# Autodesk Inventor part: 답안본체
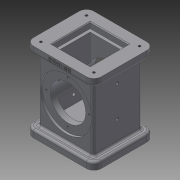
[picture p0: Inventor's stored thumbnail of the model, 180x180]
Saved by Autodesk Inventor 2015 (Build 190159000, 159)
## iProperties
Created: 2017-08
Part Number: 답안본체
Material: 일반
Document SubType Name: Modeling
Designer: Administrator
Density: 1 g/cm^3
Appearance: 기본값
Author: Administrator
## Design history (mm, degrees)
sketch "스케치1"
  geometry: L1 (-46, 41)-(46, 41); L2 (46, 41)-(46, -41); L3 (46, -41)-(-46, -41); L4 (-46, -41)-(-46, 41); L5 (-46, 41)-(46, -41); 2 further points
  constraints: 10 end point, 2 parallel, 1 coincident, 1 horizontal, 1 midpoint, 1 perpendicular
  dimensions: "d0" = 92 distance of L1.start L1.end; "d1" = 82 distance of L3.end L1.start
extrude "돌출1" new body sketch "스케치1" distance "d2" = 10; taper "d3" = 0 deg
sketch "스케치2"
  geometry: L1 (-37, 33)-(37, 33); L2 (37, 33)-(37, -33); L3 (37, -33)-(-37, -33); L4 (-37, -33)-(-37, 33); L5 (-37, 33)-(37, -33); 2 further points
  constraints: 10 end point, 2 parallel, 1 coincident, 1 horizontal, 1 midpoint, 1 perpendicular
  dimensions: "d4" = 74 distance of L1.start L1.end; "d5" = 66 distance of L3.end L1.start
extrude "돌출2" join sketch "스케치2" distance "d6" = 88; taper "d7" = 0 deg
sketch "스케치3"
  geometry: L1 (37, 33)-(37, -33) reference; L2 (37, -33)-(-37, -33) reference; L3 (-37, -33)-(-37, 33) reference; L4 (-37, 33)-(37, 33) reference; L5 (46, 41)-(-46, 41) reference; L6 (-46, 41)-(-46, -41) reference; L7 (-46, -41)-(46, -41) reference; L8 (46, -41)-(46, 41) reference; L9 (-46, 41)-(46, 41); L10 (46, 41)-(46, -41); L11 (46, -41)-(-46, -41); L12 (-46, -41)-(-46, 41); 1 further point
  constraints: 8 end point, 2 parallel, 1 horizontal, 1 perpendicular
extrude "돌출3" join sketch "스케치3" distance "d8" = 10; taper "d9" = 0 deg
sketch "스케치4"
  geometry: L1 (24, -24)-(-24, -24); L2 (-24, -24)-(-24, 24); L3 (-24, 24)-(24, 24); L4 (24, 24)-(24, -24); L5 (24, -24)-(-24, 24); 2 further points
  constraints: 10 end point, 2 parallel, 1 coincident, 1 horizontal, 1 midpoint, 1 perpendicular
  dimensions: "d10" = 48 distance of L1.start L1.end; "d11" = 48 distance of L3.end L1.start
extrude "돌출4" cut sketch "스케치4" distance "d12" = 16; taper "d13" = 0 deg
sketch "스케치6"
  geometry: L1 (-26, 26)-(26, 26); L2 (26, 26)-(26, -26); L3 (26, -26)-(-26, -26); L4 (-26, -26)-(-26, 26); L5 (-26, 26)-(26, -26); 2 further points
  constraints: 10 end point, 2 parallel, 1 coincident, 1 horizontal, 1 midpoint, 1 perpendicular
  dimensions: "d18" = 52 distance of L1.start L1.end; "d19" = 52 distance of L3.end L1.start
extrude "돌출6" cut sketch "스케치6" distance "d20" = 8; taper "d21" = 0 deg
sketch "스케치7"
  geometry: L1 (-22, 22)-(22, 22); L2 (22, 22)-(22, -22); L3 (22, -22)-(-22, -22); L4 (-22, -22)-(-22, 22); L5 (-22, 22)-(22, -22); 2 further points
  constraints: 10 end point, 2 parallel, 1 coincident, 1 horizontal, 1 midpoint, 1 perpendicular
  dimensions: "d22" = 44 distance of L1.start L1.end; "d23" = 44 distance of L3.end L1.start
extrude "돌출7" cut sketch "스케치7" distance "d24" = 74; taper "d25" = 0 deg
sketch "스케치8"
  geometry: L1 (11, 98)-(63, 98) reference; L2 (37, 98)-(37, -10); L3 (83, -10)-(-9, -10) reference; C1 r 35 at (37, 44)
  constraints: 2 end point, 2 midpoint, 1 centre point, 1 vertical
  dimensions: "d26" = 70 diameter of C1; "d27" = 54 distance from line of L3 C1.centre
extrude "돌출8" cut sketch "스케치8" distance "d28" = 3; taper "d29" = 0 deg
sketch "스케치10"
  geometry: C1 r 35 at (0, 0) reference; C2 r 24 at (0, 0); 1 further point
  constraints: 1 centre point, 1 coincident
  dimensions: "d30" = 48 diameter of C2
extrude "돌출9" cut sketch "스케치10" stored distance "d31" = 3; taper "d32" = 0 deg
sketch "스케치11"
  geometry: L1 (0, 0)-(0, -29); C1 r 24 at (0, 0) reference; C2 r 35 at (0, 0) reference; 2 further points
  constraints: 2 end point, 1 coincident, 1 vertical
  dimensions: "d33" = 29 distance of L1.start L1.end
hole "구멍1" sketch "스케치11" at (0, -29) diameter "d34" = 3.242; stored, may be unused: countersink angle "d38" = 90 deg, drill point angle "d40" = 118 deg; dims "d35" = 4, "d36" = 4, "d37" = 2, "d39" = 6
fillet "모깎기1" dims "d44" = 10
fillet "모깎기2" dims "d45" = 10
sketch "스케치12"
  geometry: L1 (-46, 31)-(-46, -31) reference; L2 (-36, -41)-(36, -41) reference; L3 (46, -31)-(46, 31) reference; L4 (36, 41)-(-36, 41) reference; L5 (-26, -26)-(-26, 26) reference; L6 (-26, 26)-(26, 26) reference; L7 (26, 26)-(26, -26) reference; L8 (26, -26)-(-26, -26) reference; A1 r 10 centre (-36, 31) between (-36, 41) and (-46, 31) reference; A2 r 10 centre (-36, -31) between (-46, -31) and (-36, -41) reference; A3 r 10 centre (36, -31) between (36, -41) and (46, -31) reference; A4 r 10 centre (36, 31) between (46, 31) and (36, 41) reference; 5 further points
  constraints: 4 coincident
hole "구멍2" sketch "스케치12" at (-36, 31), (36, 31), (36, -31), (-36, -31) diameter "d46" = 3.242; stored, may be unused: countersink angle "d50" = 90 deg, drill point angle "d52" = 118 deg; dims "d47" = 4, "d48" = 4, "d49" = 2, "d51" = 6
sketch "스케치13"
  geometry: L1 (24, 24)-(24, -24) reference; L2 (24, -24)-(-24, -24) reference; L3 (-24, -24)-(-24, 24) reference; L4 (-24, 24)-(24, 24) reference; L5 (36, 41)-(-36, 41) reference; L6 (-46, 31)-(-46, -31) reference; L7 (-36, -41)-(36, -41) reference; L8 (46, -31)-(46, 31) reference; C1 r 1.621 at (36, -31) reference; C2 r 1.621 at (-36, -31) reference; C3 r 1.621 at (-36, 31) reference; C4 r 1.621 at (36, 31) reference; A1 r 10 centre (36, 31) between (46, 31) and (36, 41) reference; A2 r 10 centre (-36, 31) between (-36, 41) and (-46, 31) reference; A3 r 10 centre (-36, -31) between (-46, -31) and (-36, -41) reference; A4 r 10 centre (36, -31) between (36, -41) and (46, -31) reference; 5 further points
  constraints: 4 coincident
hole "구멍3" sketch "스케치13" at (36, -31), (-36, -31), (-36, 31), (36, 31) diameter "d53" = 3.242; stored, may be unused: countersink angle "d57" = 90 deg, drill point angle "d59" = 118 deg; dims "d54" = 4, "d55" = 4, "d56" = 2, "d58" = 6
sketch "스케치14"
  geometry: L1 (-98, 64)-(-98, 2) reference; L2 (-98, 33)-(10, 33); L3 (10, 64)-(10, 2) reference; 2 further points
  constraints: 2 end point, 2 point on line, 1 horizontal, 1 midpoint
  dimensions: "d60" = 38 distance from line of point (-28, 33) L3; "d61" = 42 distance of point (-70, 33) point (-28, 33)
hole "구멍4" sketch "스케치14" at (-28, 33), (-70, 33) diameter "d62" = 4.134; stored, may be unused: countersink angle "d66" = 90 deg, drill point angle "d68" = 118 deg; dims "d63" = 10, "d64" = 4, "d65" = 2, "d67" = 6
fillet "모깎기3" dims "d69" = 3
fillet "모깎기4" dims "d70" = 3
fillet "모깎기5" dims "d71" = 3
fillet "모깎기6" dims "d72" = 3
sketch "스케치16"
  geometry: L1 (13.757, 6.644)-(58.243, 6.644); L2 (58.243, 6.644)-(58.243, -14.644); L3 (58.243, -14.644)-(13.757, -14.644); L4 (13.757, -14.644)-(13.757, 6.644); L5 (13.757, -14.644)-(58.243, 6.644); L6 (-10, 0)-(-10, -7) reference; L7 (36, -14.644)-(36, 6.644); L8 (13.757, -4)-(58.243, -4); L9 (0, 0)-(72, 0) reference; 1 further point
  constraints: 6 end point, 4 midpoint, 2 other
  dimensions: "d73" = 46 distance between parallel lines of L6 L7; "d74" = 4 distance between parallel lines of L8 L9
feature "엠보싱1" sketch "스케치16" dims "d0" = 92, "d1" = 82, "d75" = 0.5, "d76" = 0
chamfer "모따기1" distance "d77" = 1; stored, may be unused: second distance "d78" = 2, angle "d79" = 45 deg
chamfer "모따기2" distance "d80" = 1; stored, may be unused: second distance "d81" = 2, angle "d82" = 45 deg
node "솔리드1"
mirror "대칭1"
pattern_circular "원형 패턴1" dims angle "d42" = 360 deg
mirror "대칭2"
node "투영된 루프1"
node "투영된 루프2"
node "투영된 루프3"
node "투영된 루프4"
node "투영된 루프5"
